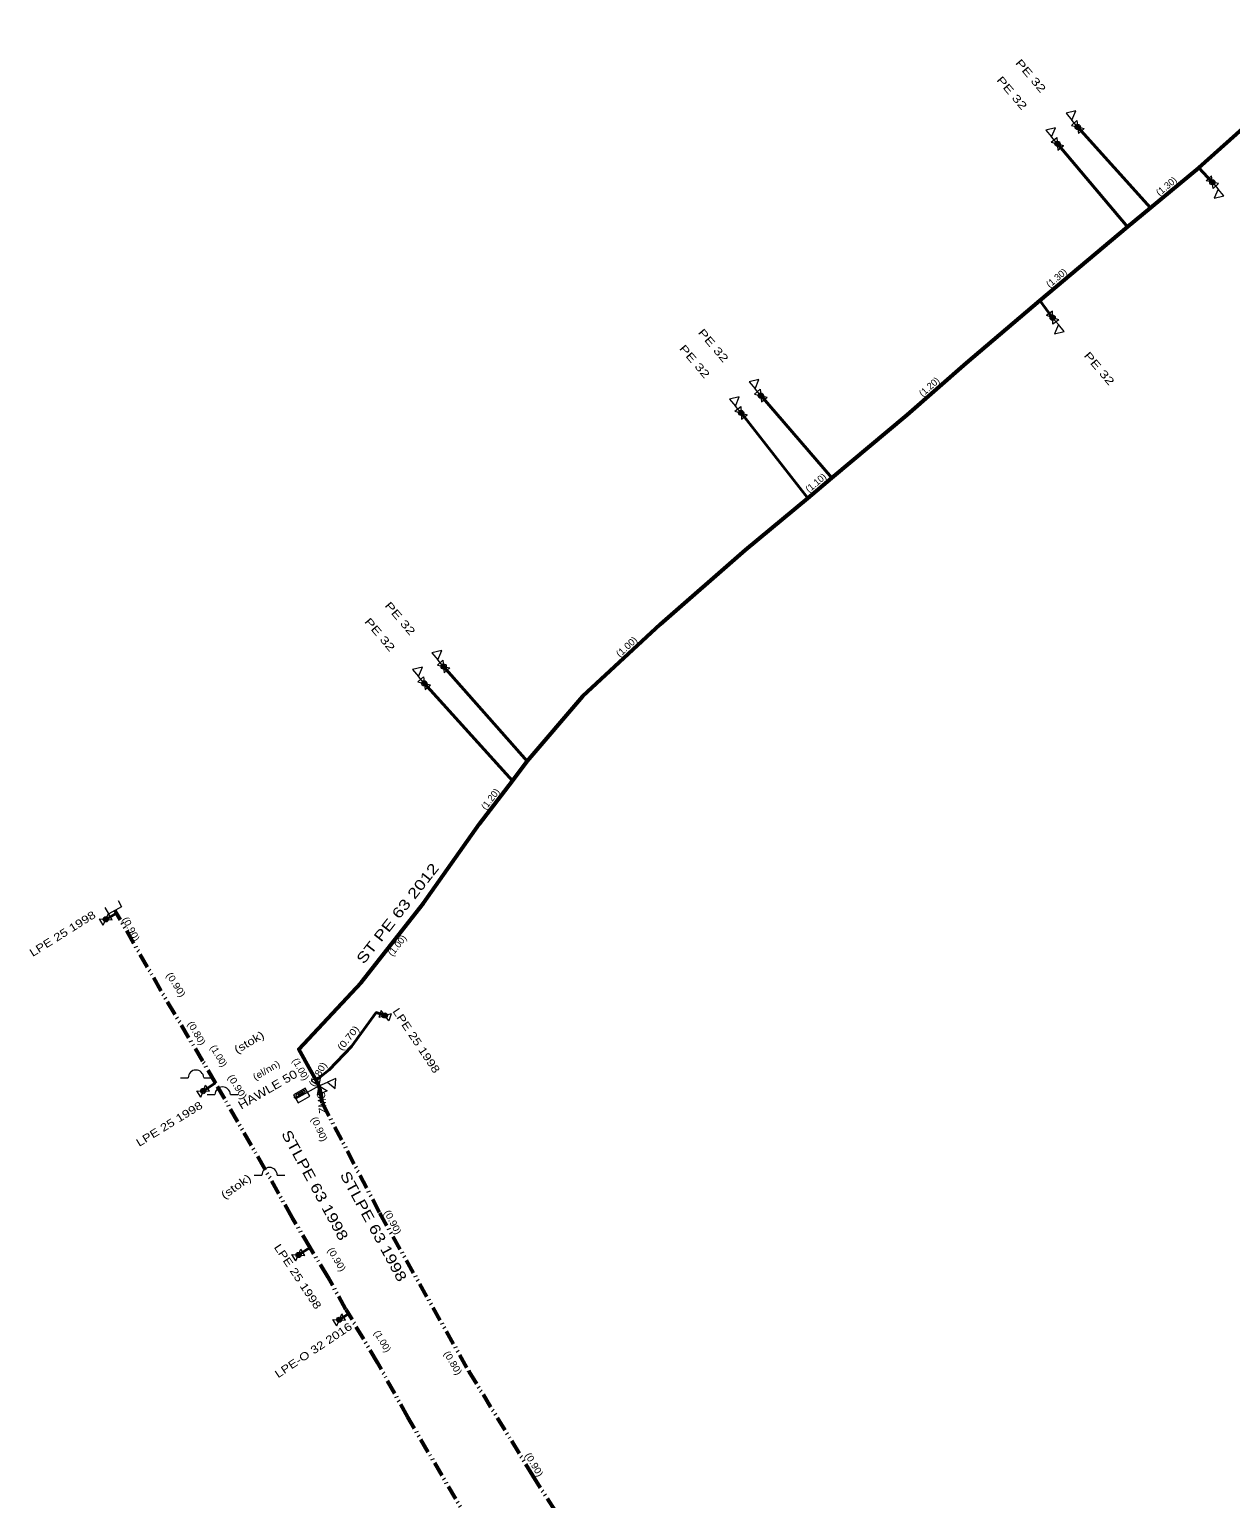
# Model space of a CAD drawing. Extents: x -648036 to -642998, y -1161549 to -1158141.
# Drawn here: x -644583.2 to -644467.9, y -1159942.6 to -1159801.6 of the extents above; entities that cross this region are included whole.
import ezdxf
from ezdxf.enums import TextEntityAlignment as Align

# ---------------------------------------------------------------- set-up
doc = ezdxf.new("R2010")
doc.units = 0
doc.header["$LTSCALE"] = 0.28
doc.header["$PDMODE"] = 32
doc.header["$PDSIZE"] = 0.14
doc.linetypes.add('DASH_DOUBLE_DOT', pattern=[9.2, 5, -1.2, 0.3, -1.2, 0.3, -1.2])
for name, color, linetype, lineweight in [('12', 7, 'DASH_DOUBLE_DOT', 40), ('15', 7, 'Continuous', 13), ('19', 7, 'Continuous', 13), ('8', 7, 'Continuous', 53)]:
    doc.layers.add(name, color=color, linetype=linetype, lineweight=lineweight)
for name, color, linetype in [('20', 7, 'Continuous'), ('22', 7, 'Continuous'), ('27', 7, 'Continuous'), ('28', 7, 'Continuous'), ('35', 7, 'Continuous')]:
    doc.layers.add(name, color=color, linetype=linetype)

msp = doc.modelspace()

# ---------------------------------------------------------------- linework, layer by layer
at = {"layer": '12', "linetype": 'Continuous'}
for p, q in [((-644475.63, -1159818.69), (-644482.6, -1159810.92)), ((-644477.82, -1159820.51), (-644484.55, -1159812.53)), ((-644470.98, -1159814.83), (-644469.68, -1159816.22)), ((-644486.24, -1159827.56), (-644485.01, -1159829.22)), ((-644506.2, -1159844.59), (-644513.02, -1159836.7)), ((-644508.51, -1159846.53), (-644514.91, -1159838.36)), ((-644535.44, -1159871.78), (-644543.47, -1159862.7)), ((-644536.87, -1159873.68), (-644545.33, -1159864.31)), ((-644565.38, -1159902.66), (-644566.56, -1159903.45)), ((-644557.41, -1159919.18), (-644556.28, -1159918.48)), ((-644553.495, -1159925.403), (-644552.59, -1159924.82))]:
    msp.add_line(p, q, dxfattribs=at)
at = {"layer": '12'}
msp.add_line((-644575.9, -1159886.97), (-644574.86, -1159886.36), dxfattribs=at)
at = {"layer": '12', "linetype": 'Continuous'}
msp.add_lwpolyline([(-644555.712, -1159902.416), (-644554.46, -1159901.42), (-644552.31, -1159899.18), (-644549.94, -1159895.92), (-644549.11, -1159896.2)], dxfattribs=at)
at = {"layer": '15'}
for p, q in [((-644483.202, -1159810.783), (-644482.672, -1159810.307)), ((-644483.202, -1159810.783), (-644481.998, -1159811.057)), ((-644482.6, -1159810.92), (-644483.155, -1159810.267)), ((-644482.672, -1159810.307), (-644482.529, -1159811.532)), ((-644482.529, -1159811.532), (-644481.998, -1159811.057)), ((-644485.147, -1159812.374), (-644484.603, -1159811.915)), ((-644485.147, -1159812.374), (-644483.953, -1159812.686)), ((-644484.55, -1159812.53), (-644485.105, -1159811.877)), ((-644484.603, -1159811.915), (-644484.498, -1159813.144)), ((-644484.498, -1159813.144), (-644483.953, -1159812.686)), ((-644469.764, -1159815.609), (-644470.284, -1159816.095)), ((-644469.596, -1159816.831), (-644469.764, -1159815.609)), ((-644469.076, -1159816.345), (-644470.284, -1159816.095)), ((-644469.68, -1159816.22), (-644469.125, -1159816.873)), ((-644469.076, -1159816.345), (-644469.596, -1159816.831)), ((-644485.023, -1159828.604), (-644485.596, -1159829.027)), ((-644484.424, -1159829.413), (-644485.596, -1159829.027)), ((-644484.996, -1159829.837), (-644485.023, -1159828.604)), ((-644485.01, -1159829.22), (-644484.455, -1159829.873)), ((-644484.424, -1159829.413), (-644484.996, -1159829.837)), ((-644513.619, -1159836.552), (-644513.08, -1159836.086)), ((-644513.619, -1159836.552), (-644512.421, -1159836.848)), ((-644513.02, -1159836.7), (-644513.575, -1159836.047)), ((-644513.08, -1159836.086), (-644512.96, -1159837.313)), ((-644512.96, -1159837.313), (-644512.421, -1159836.848)), ((-644515.501, -1159838.183), (-644514.941, -1159837.744)), ((-644515.501, -1159838.183), (-644514.319, -1159838.537)), ((-644514.91, -1159838.36), (-644515.465, -1159837.707)), ((-644514.941, -1159837.744), (-644514.88, -1159838.976)), ((-644514.88, -1159838.976), (-644514.319, -1159838.537)), ((-644544.071, -1159862.558), (-644543.537, -1159862.087)), ((-644543.47, -1159862.7), (-644544.025, -1159862.047)), ((-644543.537, -1159862.087), (-644543.403, -1159863.313)), ((-644545.932, -1159864.174), (-644545.404, -1159863.697)), ((-644545.33, -1159864.31), (-644545.885, -1159863.657)), ((-644545.404, -1159863.697), (-644545.257, -1159864.922)), ((-644544.071, -1159862.558), (-644542.869, -1159862.842)), ((-644543.403, -1159863.313), (-644542.869, -1159862.842)), ((-644545.932, -1159864.174), (-644544.728, -1159864.446)), ((-644545.257, -1159864.922), (-644544.728, -1159864.446)), ((-644576.515, -1159886.918), (-644575.286, -1159887.023)), ((-644576.155, -1159887.532), (-644576.515, -1159886.918)), ((-644576.155, -1159887.532), (-644575.645, -1159886.408)), ((-644575.286, -1159887.023), (-644575.645, -1159886.408)), ((-644549.473, -1159895.702), (-644549.701, -1159896.376)), ((-644548.519, -1159896.024), (-644549.701, -1159896.376)), ((-644548.746, -1159896.698), (-644549.473, -1159895.702)), ((-644548.519, -1159896.024), (-644548.746, -1159896.698)), ((-644568.725, -1159902.175), (-644567.99, -1159902.174)), ((-644566.781, -1159904.026), (-644566.339, -1159902.874)), ((-644566.504, -1159902.174), (-644565.77, -1159902.175)), ((-644565.944, -1159903.466), (-644566.339, -1159902.874)), ((-644555.42, -1159902.94), (-644557.656, -1159904.186)), ((-644555.42, -1159902.94), (-644554.633, -1159902.6)), ((-644567.177, -1159903.435), (-644565.944, -1159903.466)), ((-644566.781, -1159904.026), (-644567.177, -1159903.435)), ((-644566.165, -1159903.795), (-644565.43, -1159903.794)), ((-644563.944, -1159903.794), (-644563.21, -1159903.795)), ((-644557.725, -1159904.063), (-644557.656, -1159904.186)), ((-644557.477, -1159903.844), (-644556.922, -1159903.534)), ((-644561.655, -1159911.525), (-644560.92, -1159911.524)), ((-644559.434, -1159911.524), (-644558.7, -1159911.525)), ((-644557.651, -1159919.748), (-644557.169, -1159918.612)), ((-644556.795, -1159919.218), (-644557.169, -1159918.612)), ((-644558.026, -1159919.143), (-644556.795, -1159919.218)), ((-644557.651, -1159919.748), (-644558.026, -1159919.143)), ((-644554.111, -1159925.366), (-644552.88, -1159925.441)), ((-644553.736, -1159925.971), (-644554.111, -1159925.366)), ((-644553.736, -1159925.971), (-644553.254, -1159924.835)), ((-644552.88, -1159925.441), (-644553.254, -1159924.835))]:
    msp.add_line(p, q, dxfattribs=at)
for points in [[(-644483.155, -1159810.267), (-644482.783, -1159809.38), (-644483.718, -1159809.604)], [(-644485.105, -1159811.877), (-644484.733, -1159810.99), (-644485.668, -1159811.214)], [(-644469.125, -1159816.873), (-644469.497, -1159817.76), (-644468.562, -1159817.536)], [(-644484.455, -1159829.873), (-644484.827, -1159830.76), (-644483.892, -1159830.536)], [(-644513.575, -1159836.047), (-644513.203, -1159835.16), (-644514.138, -1159835.384)], [(-644515.465, -1159837.707), (-644515.093, -1159836.82), (-644516.028, -1159837.044)], [(-644544.025, -1159862.047), (-644543.653, -1159861.16), (-644544.588, -1159861.384)], [(-644545.885, -1159863.657), (-644545.513, -1159862.77), (-644546.448, -1159862.994)], [(-644556.326, -1159903.942), (-644556.749, -1159903.183), (-644557.867, -1159903.807), (-644557.444, -1159904.565)], [(-644555.42, -1159902.94), (-644554.649, -1159903.44), (-644555.585, -1159903.844), (-644555.255, -1159902.036), (-644556.191, -1159902.44)], [(-644554.633, -1159902.6), (-644553.894, -1159903.215), (-644553.834, -1159902.255)], [(-644556.742, -1159903.549), (-644556.843, -1159903.365), (-644557.68, -1159903.831), (-644557.577, -1159904.015)]]:
    msp.add_lwpolyline(points, close=True, dxfattribs=at)
msp.add_lwpolyline([(-644574.729, -1159885.15), (-644574.384, -1159885.765), (-644575.616, -1159886.455), (-644575.96, -1159885.84)], dxfattribs=at)
for centre in [(-644567.2474, -1159902.1746), (-644564.6874, -1159903.7946), (-644560.1774, -1159911.5246)]:
    msp.add_arc(centre, 0.7431, 1.2748, 179.83951, dxfattribs=at)
msp.add_point((-644557.725, -1159904.063), dxfattribs=at)
at = {"layer": '19'}
for centre, radius in [((-644482.6, -1159810.92), 0.25), ((-644482.6, -1159810.92), 0.17), ((-644482.6, -1159810.92), 0.09), ((-644484.55, -1159812.53), 0.25), ((-644484.55, -1159812.53), 0.17), ((-644484.55, -1159812.53), 0.09), ((-644469.68, -1159816.22), 0.25), ((-644469.68, -1159816.22), 0.17), ((-644469.68, -1159816.22), 0.09), ((-644485.01, -1159829.22), 0.25), ((-644485.01, -1159829.22), 0.17), ((-644485.01, -1159829.22), 0.09), ((-644513.02, -1159836.7), 0.25), ((-644513.02, -1159836.7), 0.17), ((-644513.02, -1159836.7), 0.09), ((-644514.91, -1159838.36), 0.25), ((-644514.91, -1159838.36), 0.17), ((-644514.91, -1159838.36), 0.09), ((-644543.47, -1159862.7), 0.25), ((-644543.47, -1159862.7), 0.17), ((-644543.47, -1159862.7), 0.09), ((-644545.33, -1159864.31), 0.25), ((-644545.33, -1159864.31), 0.17), ((-644545.33, -1159864.31), 0.09), ((-644575.9, -1159886.97), 0.25), ((-644575.9, -1159886.97), 0.17), ((-644575.9, -1159886.97), 0.09), ((-644549.11, -1159896.2), 0.25), ((-644549.11, -1159896.2), 0.17), ((-644549.11, -1159896.2), 0.09), ((-644566.56, -1159903.45), 0.25), ((-644566.56, -1159903.45), 0.17), ((-644566.56, -1159903.45), 0.09), ((-644557.41, -1159919.18), 0.25), ((-644557.41, -1159919.18), 0.17), ((-644557.41, -1159919.18), 0.09), ((-644553.495, -1159925.403), 0.25), ((-644553.495, -1159925.403), 0.17), ((-644553.495, -1159925.403), 0.09)]:
    msp.add_circle(centre, radius, dxfattribs=at)
at = {"layer": '8'}
for points in [[(-644470.98, -1159814.83), (-644460.73, -1159805.69), (-644456.33, -1159802.04), (-644455.72, -1159801.55)], [(-644506.2, -1159844.59), (-644498.97, -1159838.55), (-644493.29, -1159833.55), (-644486.24, -1159827.56), (-644477.82, -1159820.51), (-644475.63, -1159818.69), (-644470.98, -1159814.83)], [(-644535.44, -1159871.78), (-644530.1, -1159865.54), (-644522.64, -1159858.63), (-644514.5, -1159851.49), (-644508.51, -1159846.53), (-644506.2, -1159844.59)], [(-644555.712, -1159902.416), (-644556.21, -1159901.52), (-644557.36, -1159899.43), (-644551.39, -1159893.03), (-644545.39, -1159885.41), (-644540.02, -1159877.81), (-644536.87, -1159873.68), (-644535.44, -1159871.78)], [(-644555.146, -1159904.577), (-644555.23, -1159903.79), (-644555.42, -1159902.94), (-644555.712, -1159902.416)], [(-644552.86, -1159924.4), (-644552.59, -1159924.82), (-644552.28, -1159925.35)]]:
    msp.add_lwpolyline(points, dxfattribs=at)
at = {"layer": '8', "linetype": 'DASH_DOUBLE_DOT'}
for points in [[(-644565.38, -1159902.66), (-644566.59, -1159900.58), (-644570.61, -1159893.81), (-644574.86, -1159886.36), (-644575, -1159886.11)], [(-644556.28, -1159918.48), (-644558.01, -1159915.58), (-644560.62, -1159910.93), (-644564.48, -1159904.21), (-644565.38, -1159902.66)], [(-644555.146, -1159904.577), (-644549.63, -1159915.13), (-644541.05, -1159930.36), (-644534.94, -1159940.34), (-644531.51, -1159945.73)], [(-644552.86, -1159924.4), (-644554.57, -1159921.3), (-644556.28, -1159918.48)], [(-644537.53, -1159950.99), (-644539.67, -1159947.1), (-644546.9, -1159934.75), (-644549.81, -1159929.51), (-644552.28, -1159925.35)]]:
    msp.add_lwpolyline(points, dxfattribs=at)

# ---------------------------------------------------------------- texts
at = {"layer": '15'}
msp.add_text('ZMS', height=0.75, rotation=96.092, dxfattribs=at).set_placement((-644554.7742, -1159904.5273), align=Align.CENTER)
at = {"layer": '20'}
for s, rotation, width, p in [('ST PE 63 2012', 51.783, 1.3, (-644547.4992, -1159886.7078)), ('STLPE 63 1998', 298.511, 1.25, (-644556.2651, -1159912.7218)), ('STLPE 63 1998', 298.511, 1.25, (-644550.6351, -1159916.6718))]:
    msp.add_text(s, height=1, rotation=rotation, dxfattribs=dict(at, width=width)).set_placement(p, align=Align.CENTER)
at = {"layer": '22'}
for s, rotation, width, p in [('PE 32', 310.308, 1.4, (-644487.3952, -1159806.2509)), ('PE 32', 310.308, 1.4, (-644489.2062, -1159807.8939)), ('PE 32', 310.334, 1.4, (-644517.8667, -1159832.1293)), ('PE 32', 310.334, 1.4, (-644519.6607, -1159833.6603)), ('PE 32', 310.355, 1.4, (-644480.8224, -1159834.3377)), ('PE 32', 310.326, 1.4, (-644547.931, -1159858.3313)), ('PE 32', 310.326, 1.4, (-644549.88, -1159859.8753)), ('LPE 25 1998', 32.086, 1.25, (-644579.8537, -1159888.6601)), ('LPE 25 1998', 303.668, 1.25, (-644546.404, -1159898.8086)), ('LPE 25 1998', 31.513, 1.25, (-644569.609, -1159906.9227)), ('LPE 25 1998', 303.668, 1.25, (-644557.784, -1159921.4586)), ('LPE-O 32 2016', 33.668, 1.25, (-644555.7644, -1159928.6313))]:
    msp.add_text(s, height=0.75, rotation=rotation, dxfattribs=dict(at, width=width)).set_placement(p, align=Align.CENTER)
at = {"layer": '27'}
for s, rotation, p in [('(1.30)', 39.696, (-644473.8816, -1159816.849)), ('(1.30)', 39.939, (-644484.4296, -1159825.6532)), ('(1.20)', 41.357, (-644496.6397, -1159836.0982)), ('(1.10)', 40.024, (-644507.5345, -1159845.3187)), ('(1.20)', 52.667, (-644538.7261, -1159875.6181)), ('(1.00)', 51.783, (-644547.6782, -1159889.6741)), ('(1.00)', 300.803, (-644565.3355, -1159900.2336)), ('(1.00)', 298.821, (-644557.4718, -1159901.5043)), ('(1.00)', 300.803, (-644549.6155, -1159927.6236))]:
    msp.add_text(s, height=0.65, rotation=rotation, dxfattribs=at).set_placement(p, align=Align.CENTER)
for s, rotation, width, p in [('(1.00)', 42.808, 1.05, (-644525.6859, -1159861.0415)), ('(0.90)', 297.938, 1.1, (-644573.7581, -1159888.0497)), ('(0.90)', 302.522, 1.15, (-644569.4342, -1159893.4073)), ('(0.80)', 300.23, 1.1, (-644567.4561, -1159898.0479)), ('(0.70)', 50.993, 1.2, (-644552.3829, -1159898.5621)), ('(el/nn)', 30.367, 1.15, (-644560.3298, -1159901.7346)), ('(0.80)', 60.161, 1.1, (-644555.2684, -1159901.9937)), ('(0.90)', 301.949, 1.15, (-644563.5386, -1159903.213)), ('(0.90)', 294.5, 1.1, (-644555.6913, -1159907.2302)), ('(0.90)', 297.938, 1.1, (-644548.6281, -1159916.1797)), ('(0.90)', 300.803, 1.1, (-644554.0049, -1159919.7761)), ('(0.80)', 300.803, 1.1, (-644542.853, -1159929.7021)), ('(0.90)', 300.803, 1.1, (-644535.0549, -1159939.4661))]:
    msp.add_text(s, height=0.65, rotation=rotation, dxfattribs=dict(at, width=width)).set_placement(p, align=Align.CENTER)
at = {"layer": '28'}
for rotation, width, p in [(30.94, 1.25, (-644561.9558, -1159899.0822)), (35.523, 1.3, (-644563.1874, -1159912.913))]:
    msp.add_text('(stok)', height=0.75, rotation=rotation, dxfattribs=dict(at, width=width)).set_placement(p, align=Align.CENTER)
at = {"layer": '35', "width": 1.2}
msp.add_text('HAWLE 50', height=0.8, rotation=30.123, dxfattribs=at).set_placement((-644560.1602, -1159903.6419), align=Align.CENTER)

doc.saveas('drawing.dxf')
